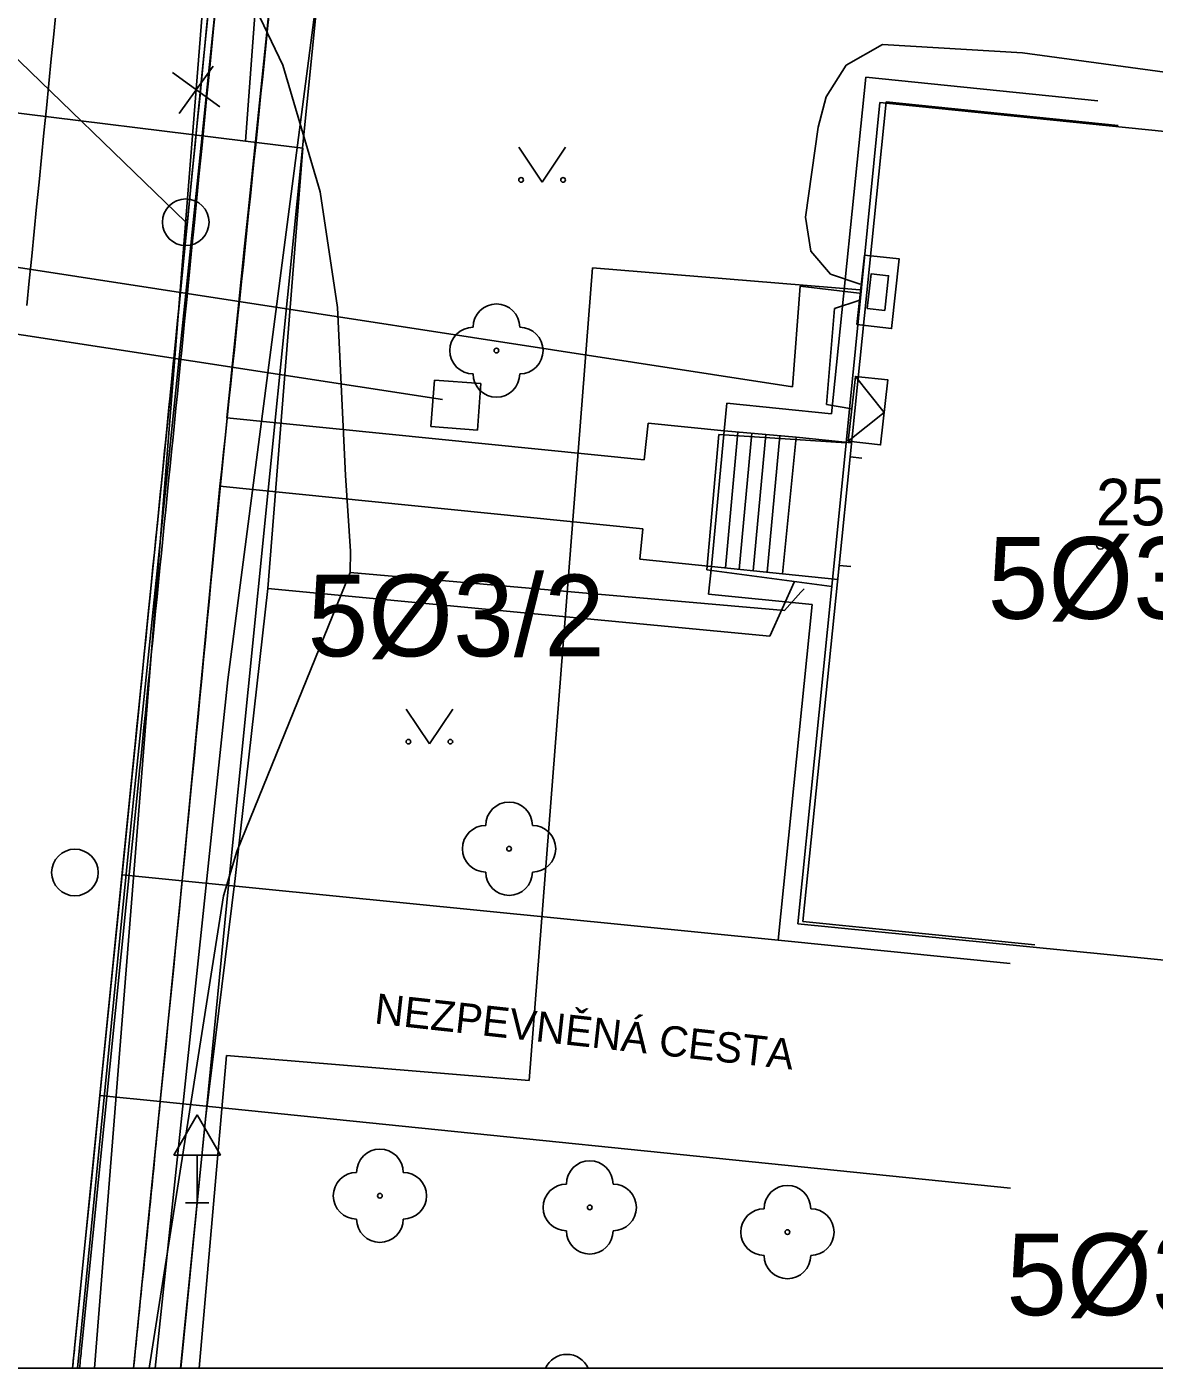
# Model space of a CAD drawing. Extents: x -643342 to -638635, y -1201752 to -1189948.
# Drawn here: x -639502.29 to -639478.12, y -1192858.61 to -1192829.85 of the extents above; entities that cross this region are included whole.
import ezdxf

# ---------------------------------------------------------------- set-up
doc = ezdxf.new("R2010")
doc.units = 0
for name, color, linetype in [('IS_EL_NN_NADZEMNÍ', 7, 'Continuous'), ('IS_EL_NN_PODZEMNÍ', 7, 'Continuous'), ('IS_PLYN_STL', 7, 'Continuous'), ('IS_TELEF_MISTNI_ZAMERENO', 7, 'Continuous'), ('IS_VODOVOD_PRIPOJKA DOMOVNÍ', 7, 'Continuous'), ('K-HRANICE_KN', 7, 'Continuous'), ('K-SLUCKOVE CARY', 7, 'Continuous'), ('K-ČÍSLA_PARCEL', 7, 'Continuous'), ('kanalizace_dešťová_stávající', 7, 'Continuous'), ('N-KAN_DEST_SACHTY-NÁVRH', 7, 'Continuous'), ('N-KAN_DEST_TRASA-NÁVRH', 7, 'Continuous'), ('N-OBVOD STAVBY 06', 7, 'Continuous'), ('N-OSA', 7, 'Continuous'), ('N-rusene_vedeni', 7, 'Continuous'), ('N-SILNICE', 7, 'Continuous'), ('N-SRAFY_PLOCHY', 7, 'Continuous'), ('Vrstva 13', 7, 'Continuous'), ('Z-budovy', 7, 'Continuous'), ('Z-hrany_a_čáry', 7, 'Continuous'), ('Z-popisy', 7, 'Continuous'), ('Z-stromy', 7, 'Continuous'), ('Z-vchody_vjezdy', 7, 'Continuous'), ('Z-značky', 7, 'Continuous'), ('Z-šachty_poklopy', 7, 'Continuous')]:
    doc.layers.add(name, color=color, linetype=linetype)

msp = doc.modelspace()

# ---------------------------------------------------------------- linework, layer by layer
at = {"layer": 'IS_EL_NN_NADZEMNÍ'}
msp.add_lwpolyline([(-639484.677, -1192838.735), (-639483.905, -1192838.117), (-639484.523, -1192837.344)], dxfattribs=at)
at = {"layer": 'IS_EL_NN_PODZEMNÍ'}
for p, q in [((-639483.94, -1192830.23), (-639484.72, -1192830.67)), ((-639480.94, -1192830.41), (-639483.94, -1192830.23)), ((-639475.43, -1192831.15), (-639480.94, -1192830.41)), ((-639484.72, -1192830.67), (-639485.15, -1192831.35)), ((-639485.15, -1192831.35), (-639485.32, -1192832)), ((-639485.32, -1192832), (-639485.59, -1192833.93)), ((-639485.59, -1192833.93), (-639485.48, -1192834.66)), ((-639506.96, -1192834.32), (-639485.87, -1192837.57)), ((-639485.48, -1192834.66), (-639485.06, -1192835.15)), ((-639490.16, -1192835.02), (-639491.52, -1192852.44)), ((-639484.43, -1192835.49), (-639490.16, -1192835.02)), ((-639485.06, -1192835.15), (-639484.42, -1192835.37)), ((-639485.87, -1192837.57), (-639485.71, -1192835.41)), ((-639485.71, -1192835.41), (-639484.44, -1192835.56)), ((-639484.97, -1192835.89), (-639485.14, -1192837.95)), ((-639484.45, -1192835.72), (-639484.97, -1192835.89)), ((-639485.14, -1192837.95), (-639484.6, -1192838.04)), ((-639498.01, -1192851.9), (-639498.598, -1192858.606)), ((-639491.52, -1192852.44), (-639498.01, -1192851.9))]:
    msp.add_line(p, q, dxfattribs=at)
for points in [[(-639484.493, -1192836.235), (-639484.327, -1192834.745), (-639483.582, -1192834.827), (-639483.747, -1192836.318)], [(-639484.27, -1192835.886), (-639484.188, -1192835.146), (-639483.812, -1192835.188), (-639483.894, -1192835.928)], [(-639484.677, -1192838.735), (-639484.523, -1192837.344), (-639483.827, -1192837.421), (-639483.982, -1192838.813)]]:
    msp.add_lwpolyline(points, close=True, dxfattribs=at)
at = {"layer": 'IS_PLYN_STL'}
for points in [[(-639495.36, -1192841.55), (-639495.35, -1192841.09), (-639495.46, -1192839.47), (-639495.63, -1192835.87), (-639496, -1192833.39), (-639496.8, -1192830.67), (-639498.19, -1192827.77), (-639499.55, -1192825.67), (-639498.43, -1192813.58)], [(-639499.669, -1192858.606), (-639498.07, -1192848.48), (-639497.79, -1192847.53), (-639495.36, -1192841.55)], [(-639495.36, -1192841.55), (-639486.04, -1192842.36), (-639485.69, -1192841.97), (-639485.62, -1192841.9)]]:
    msp.add_lwpolyline(points, dxfattribs=at)
at = {"layer": 'IS_TELEF_MISTNI_ZAMERENO'}
for p, q in [((-639497.28, -1192827.88), (-639497.6, -1192832.3)), ((-639506.4, -1192831.22), (-639497.6, -1192832.3)), ((-639506.4, -1192831.22), (-639497.6, -1192832.3)), ((-639497.6, -1192832.3), (-639496.37, -1192832.45)), ((-639496.37, -1192832.45), (-639496.44, -1192833.26)), ((-639496.44, -1192833.26), (-639497.12, -1192841.89)), ((-639497.12, -1192841.89), (-639497.82, -1192848.11)), ((-639497.12, -1192841.89), (-639486.36, -1192842.91)), ((-639486.36, -1192842.91), (-639485.83, -1192841.74)), ((-639497.82, -1192848.11), (-639498.46, -1192853.26)), ((-639498.46, -1192853.26), (-639497.82, -1192848.11)), ((-639498.46, -1192853.26), (-639498.988, -1192858.606))]:
    msp.add_line(p, q, dxfattribs=at)
at = {"layer": 'IS_VODOVOD_PRIPOJKA DOMOVNÍ'}
msp.add_lwpolyline([(-639506.048, -1192835.895), (-639505.91, -1192835.917), (-639493.38, -1192837.836)], dxfattribs=at)
at = {"layer": 'K-HRANICE_KN'}
for p, q in [((-639495.88, -1192827.71), (-639497.98, -1192843.85)), ((-639484.72, -1192838.77), (-639484, -1192831.47)), ((-639484, -1192831.47), (-639472.68, -1192832.62)), ((-639487.71, -1192841.49), (-639487.45, -1192838.59)), ((-639487.45, -1192838.59), (-639484.72, -1192838.77)), ((-639484.72, -1192838.77), (-639485.03, -1192841.85)), ((-639485.03, -1192841.85), (-639487.71, -1192841.49)), ((-639485.76, -1192849.08), (-639485.03, -1192841.85)), ((-639497.98, -1192843.85), (-639499.541, -1192858.606)), ((-639474.46, -1192850.2), (-639485.76, -1192849.08))]:
    msp.add_line(p, q, dxfattribs=at)
at = {"layer": 'K-SLUCKOVE CARY'}
msp.add_line((-639484.72, -1192838.77), (-639485.03, -1192841.85), dxfattribs=at)
at = {"layer": 'K-ČÍSLA_PARCEL'}
msp.add_circle((-639479.267, -1192840.96), 0.0875, dxfattribs=at)
at = {"layer": 'kanalizace_dešťová_stávající'}
msp.add_lwpolyline([(-639500.838, -1192858.606), (-639498.4, -1192827.95), (-639495.47, -1192797.17), (-639492.53, -1192766.39), (-639489.24, -1192732.18), (-639488.56, -1192730.68), (-639487.73, -1192718.33)], dxfattribs=at)
at = {"layer": 'N-KAN_DEST_SACHTY-NÁVRH'}
msp.add_circle((-639498.884, -1192834.039), 0.5, dxfattribs=at)
at = {"layer": 'N-KAN_DEST_TRASA-NÁVRH'}
msp.add_lwpolyline([(-639498.884, -1192834.039), (-639503.116, -1192829.951), (-639498.124, -1192780.201), (-639493.988, -1192740.511), (-639490.998, -1192720.223)], dxfattribs=at)
at = {"layer": 'N-OBVOD STAVBY 06'}
msp.add_lwpolyline([(-639495.855, -1192827.243), (-639497.965, -1192848.259), (-639498.429, -1192852.99), (-639498.998, -1192858.606)], dxfattribs=at)
at = {"layer": 'N-OSA'}
msp.add_arc((-646965.2, -1192091.375), 7499.947, 354.3034191, 354.433219, dxfattribs=at)
at = {"layer": 'N-rusene_vedeni'}
for p, q in [((-639498.293, -1192830.691), (-639499.024, -1192831.705)), ((-639499.165, -1192830.832), (-639498.152, -1192831.564))]:
    msp.add_line(p, q, dxfattribs=at)
at = {"layer": 'N-SILNICE'}
for p, q in [((-639500.054, -1192846.093), (-639501.267, -1192858.169)), ((-639499.905, -1192846.108), (-639501.117, -1192858.184)), ((-639498.96, -1192848.16), (-639500.249, -1192848.031)), ((-639499.43, -1192852.89), (-639500.723, -1192852.76))]:
    msp.add_line(p, q, dxfattribs=at)
for centre, radius, start, end in [((-641512.051, -1192624.908), 2025.323, 353.912138, 354.578474), ((-646965.2, -1192091.375), 7503.197, 354.3034191, 354.433219), ((-646965.2, -1192091.375), 7503.347, 354.3034191, 354.433219), ((-654422.965, -1191345.767), 14998.142, 354.2588659, 354.2970566), ((-654422.965, -1191345.767), 14998.292, 354.2588659, 354.2970566), ((-641337.402, -1192667.87), 1847.261, 354.251674, 354.662705), ((-641310.465, -1192674.158), 1819.834, 354.182821, 354.363695), ((-642489.652, -1192559.732), 3003.25, 354.28864, 354.297053), ((-642489.652, -1192559.732), 3003.4, 354.288926, 354.297053)]:
    msp.add_arc(centre, radius, start, end, dxfattribs=at)
at = {"layer": 'N-SRAFY_PLOCHY'}
for p, q in [((-639498.336, -1192828.875), (-639498.528, -1192830.819)), ((-639497.334, -1192831.903), (-639497.098, -1192829.531)), ((-639498.865, -1192834.22), (-639498.423, -1192829.76)), ((-639498.528, -1192830.819), (-639498.744, -1192832.997)), ((-639497.62, -1192834.552), (-639497.334, -1192831.903)), ((-639498.744, -1192832.997), (-639498.975, -1192835.325)), ((-639499.398, -1192839.558), (-639498.865, -1192834.22)), ((-639497.994, -1192838.233), (-639497.62, -1192834.552)), ((-639498.975, -1192835.325), (-639499.184, -1192837.413)), ((-639499.184, -1192837.413), (-639499.342, -1192838.994)), ((-639498.354, -1192841.835), (-639497.994, -1192838.233)), ((-639499.342, -1192838.994), (-639499.555, -1192841.119)), ((-639499.76, -1192843.167), (-639499.398, -1192839.558)), ((-639499.555, -1192841.119), (-639499.715, -1192842.722)), ((-639498.573, -1192844.121), (-639498.354, -1192841.835)), ((-639499.715, -1192842.722), (-639499.92, -1192844.764)), ((-639500.194, -1192847.484), (-639499.76, -1192843.167)), ((-639498.776, -1192846.242), (-639498.573, -1192844.121)), ((-639499.92, -1192844.764), (-639500.076, -1192846.316)), ((-639498.96, -1192848.16), (-639498.776, -1192846.242)), ((-639500.076, -1192846.316), (-639500.249, -1192848.031)), ((-639500.537, -1192850.904), (-639500.194, -1192847.484)), ((-639500.249, -1192848.031), (-639500.723, -1192852.76)), ((-639500.249, -1192848.031), (-639498.96, -1192848.16)), ((-639498.96, -1192848.16), (-639500.249, -1192848.031)), ((-639499.43, -1192852.89), (-639498.96, -1192848.16)), ((-639500.895, -1192854.465), (-639500.537, -1192850.904)), ((-639500.723, -1192852.76), (-639500.886, -1192854.378)), ((-639500.723, -1192852.76), (-639499.43, -1192852.89)), ((-639499.43, -1192852.89), (-639500.723, -1192852.76)), ((-639499.627, -1192854.838), (-639499.43, -1192852.89)), ((-639501.31, -1192858.606), (-639500.895, -1192854.465)), ((-639500.886, -1192854.378), (-639501.052, -1192856.032)), ((-639499.916, -1192857.748), (-639499.627, -1192854.838)), ((-639501.052, -1192856.032), (-639501.205, -1192857.55)), ((-639501.205, -1192857.55), (-639501.31, -1192858.606)), ((-639500.004, -1192858.606), (-639499.916, -1192857.748)), ((-639507.843, -1192858.606), (-639501.31, -1192858.606)), ((-639501.31, -1192858.606), (-639500.004, -1192858.606))]:
    msp.add_line(p, q, dxfattribs=at)
at = {"layer": 'Vrstva 13'}
msp.add_lwpolyline([(-639343.591, -1192858.606), (-639343.591, -1192648.606), (-639640.591, -1192648.606), (-639640.591, -1192858.606), (-639343.591, -1192858.606)], dxfattribs=at)
at = {"layer": 'Z-budovy'}
for p, q in [((-639484.635, -1192839.069), (-639483.86, -1192831.46)), ((-639483.86, -1192831.46), (-639478.886, -1192831.967)), ((-639484.873, -1192841.398), (-639484.635, -1192839.069)), ((-639485.65, -1192849.03), (-639484.873, -1192841.398)), ((-639480.675, -1192849.534), (-639485.65, -1192849.03))]:
    msp.add_line(p, q, dxfattribs=at)
at = {"layer": 'Z-hrany_a_čáry'}
for p, q in [((-639498.003, -1192838.232), (-639496.88, -1192827.438)), ((-639498.06, -1192827.63), (-639500.02, -1192846.56)), ((-639484.3, -1192830.93), (-639485.035, -1192838.149)), ((-639479.326, -1192831.437), (-639484.3, -1192830.93)), ((-639487.28, -1192837.92), (-639487.34, -1192838.51)), ((-639485.035, -1192838.149), (-639487.28, -1192837.92)), ((-639489.05, -1192839.13), (-639498.003, -1192838.232)), ((-639488.97, -1192838.344), (-639489.05, -1192839.13)), ((-639487.34, -1192838.51), (-639488.97, -1192838.344)), ((-639487.34, -1192838.51), (-639487.61, -1192841.42)), ((-639485.79, -1192838.65), (-639487.34, -1192838.51)), ((-639487.041, -1192838.537), (-639487.311, -1192841.45)), ((-639486.742, -1192838.564), (-639487.012, -1192841.481)), ((-639486.444, -1192838.591), (-639486.715, -1192841.511)), ((-639486.145, -1192838.618), (-639486.416, -1192841.542)), ((-639486.088, -1192841.575), (-639485.79, -1192838.65)), ((-639485.79, -1192838.65), (-639484.605, -1192838.771)), ((-639498.15, -1192839.7), (-639498.96, -1192848.16)), ((-639489.08, -1192840.61), (-639498.15, -1192839.7)), ((-639489.147, -1192841.263), (-639489.08, -1192840.61)), ((-639487.61, -1192841.42), (-639489.147, -1192841.263)), ((-639487.61, -1192841.42), (-639487.67, -1192842.01)), ((-639487.61, -1192841.42), (-639486.088, -1192841.575)), ((-639486.088, -1192841.575), (-639484.903, -1192841.696)), ((-639487.67, -1192842.01), (-639485.452, -1192842.236)), ((-639485.452, -1192842.236), (-639486.18, -1192849.43)), ((-639500.02, -1192846.56), (-639501.206, -1192858.606)), ((-639498.96, -1192848.16), (-639499.43, -1192852.89)), ((-639498.96, -1192848.16), (-639486.18, -1192849.43)), ((-639486.18, -1192849.43), (-639481.205, -1192849.934)), ((-639499.43, -1192852.89), (-639500.007, -1192858.606)), ((-639499.43, -1192852.89), (-639481.2, -1192854.75))]:
    msp.add_line(p, q, dxfattribs=at)
at = {"layer": 'Z-stromy'}
for centre in [(-639492.22, -1192836.79), (-639491.95, -1192847.47), (-639494.72, -1192854.91), (-639490.22, -1192855.16), (-639485.98, -1192855.69)]:
    msp.add_circle(centre, 0.05, dxfattribs=at)
for centre, start, end in [((-639492.22, -1192836.29), 0, 180), ((-639492.72, -1192836.79), 90, 270), ((-639491.72, -1192836.79), 270, 90), ((-639492.22, -1192837.29), 180, 0), ((-639491.95, -1192846.97), 0, 180), ((-639492.45, -1192847.47), 90, 270), ((-639491.45, -1192847.47), 270, 90), ((-639491.95, -1192847.97), 180, 0), ((-639494.72, -1192854.41), 0, 180), ((-639490.22, -1192854.66), 0, 180), ((-639495.22, -1192854.91), 90, 270), ((-639494.22, -1192854.91), 270, 90), ((-639490.72, -1192855.16), 90, 270), ((-639489.72, -1192855.16), 270, 90), ((-639485.98, -1192855.19), 0, 180), ((-639486.48, -1192855.69), 90, 270), ((-639485.48, -1192855.69), 270, 90), ((-639494.72, -1192855.41), 180, 0), ((-639490.22, -1192855.66), 180, 0), ((-639485.98, -1192856.19), 180, 0), ((-639490.71, -1192858.81), 24.0463, 155.9537)]:
    msp.add_arc(centre, 0.5, start, end, dxfattribs=at)
at = {"layer": 'Z-vchody_vjezdy'}
for p, q in [((-639484.635, -1192839.069), (-639484.873, -1192841.398)), ((-639484.386, -1192839.094), (-639484.635, -1192839.069)), ((-639484.624, -1192841.423), (-639484.873, -1192841.398))]:
    msp.add_line(p, q, dxfattribs=at)
at = {"layer": 'Z-značky'}
for p, q in [((-639491.741, -1192832.433), (-639491.241, -1192833.183)), ((-639491.241, -1192833.183), (-639490.741, -1192832.433)), ((-639494.158, -1192844.475), (-639493.658, -1192845.225)), ((-639493.658, -1192845.225), (-639493.158, -1192844.475)), ((-639498.64, -1192853.176), (-639499.14, -1192854.042)), ((-639498.14, -1192854.042), (-639498.64, -1192853.176)), ((-639499.14, -1192854.042), (-639498.14, -1192854.042)), ((-639498.64, -1192854.042), (-639498.64, -1192855.06)), ((-639498.89, -1192855.06), (-639498.39, -1192855.06))]:
    msp.add_line(p, q, dxfattribs=at)
for centre in [(-639491.691, -1192833.133), (-639490.792, -1192833.133), (-639494.108, -1192845.175), (-639493.209, -1192845.175)]:
    msp.add_circle(centre, 0.05, dxfattribs=at)
at = {"layer": 'Z-šachty_poklopy'}
for p, q in [((-639493.55, -1192837.423), (-639493.627, -1192838.42)), ((-639492.553, -1192837.5), (-639493.55, -1192837.423)), ((-639492.63, -1192838.497), (-639492.553, -1192837.5)), ((-639493.627, -1192838.42), (-639492.63, -1192838.497))]:
    msp.add_line(p, q, dxfattribs=at)
msp.add_circle((-639501.26, -1192847.98), 0.5, dxfattribs=at)

# ---------------------------------------------------------------- texts
at = {"layer": 'K-ČÍSLA_PARCEL'}
for s, p in [('5%%c3/9', (-639481.687, -1192842.54)), ('5%%c3/2', (-639496.272, -1192843.345)), ('5%%c3/2', (-639481.286, -1192857.47))]:
    msp.add_text(s, height=1.75, dxfattribs=at).set_placement(p)
at = {"layer": 'Z-popisy'}
msp.add_text('259', height=1, dxfattribs=at).set_placement((-639479.365, -1192840.539))
msp.add_text('NEZPEVNĚNÁ CESTA', height=0.65, rotation=353.6919, dxfattribs=at).set_placement((-639494.856, -1192851.214))

doc.saveas('drawing.dxf')
